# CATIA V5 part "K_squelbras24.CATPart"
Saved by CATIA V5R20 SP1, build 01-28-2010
Part number: squelbras24
Publications: "Longueurbras24"
Bounding box of the stored display mesh (mm): x -160 to 0, y 0 to 0, z -15 to 15
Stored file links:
  G:\Khaled_CFAO_2011\SIL\SIL_GR2\zthiebault\Khaled\CAD_ThinkMOTION\K_squelbras24.CATPart
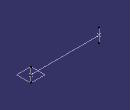
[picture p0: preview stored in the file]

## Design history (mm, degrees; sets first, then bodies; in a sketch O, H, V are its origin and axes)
Parameters
  Longueurbras24 = 160 mm
Set1 "setgéombras21"
  Point1: (0, 0, 0)
  Line1: type Normal, RefPoint Point1, RefSkin xy-plane, Start -15, End 15
  Line2: type Normal, RefPoint Point1, RefSkin yz-plane, Start -160 {= -Longueurbras24}, End 0
  Line3: type Normal, RefPoint vertex of Line2, RefSkin xy-plane, Start -15, End 15
  Plane1: type OffsetPt, RefPlane xy-plane, RefPoint vertex of Line2
  Point2: stored without definition
  Point3: (0, 0, 0), relative to vertex of Line2
Body1 (main body)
